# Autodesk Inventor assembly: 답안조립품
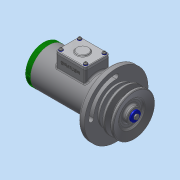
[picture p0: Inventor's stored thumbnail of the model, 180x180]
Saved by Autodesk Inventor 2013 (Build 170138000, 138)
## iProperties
Created: 2017-05
Part Number: 답안조립품
Document SubType Name: Assembly
Designer: dgall
Author: dgall
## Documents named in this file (20)
- C:\Users\dgall\Desktop\470507V1018\답안조립품.iam
- C:\Users\dgall\Desktop\470507V1018\본체.ipt
- C:\Users\dgall\Desktop\470507V1018\V-벨트풀리.ipt
- C:\Users\dgall\Desktop\470507V1018\너트 M10.ipt
- C:\Users\dgall\Desktop\470507V1018\멈춤링 15 x 1.ipt
- C:\Users\dgall\Desktop\470507V1018\멈춤링 35x1.6.ipt
- C:\Users\dgall\Desktop\470507V1018\베어링 15 x 35 x 11.ipt
- C:\Users\dgall\Desktop\470507V1018\볼트 M4 x 10.ipt
- C:\Users\dgall\Desktop\470507V1018\부시1.ipt
- C:\Users\dgall\Desktop\470507V1018\부시2.ipt
- C:\Users\dgall\Desktop\470507V1018\사이드 커버.ipt
- 사이드 커버.ipt
- C:\Users\dgall\Desktop\470507V1018\십자볼트 M3 x 10.ipt
- C:\Users\dgall\Desktop\470507V1018\오일 실 15 25 7.ipt
- C:\Users\dgall\Desktop\470507V1018\와셔 3x6.ipt
- C:\Users\dgall\Desktop\470507V1018\와셔 4x16.ipt
- C:\Users\dgall\Desktop\470507V1018\와셔 10x21.ipt
- C:\Users\dgall\Desktop\470507V1018\축.ipt
- C:\Users\dgall\Desktop\470507V1018\키 4 x 4 x 18.ipt
- C:\Users\dgall\Desktop\470507V1018\탑 커버.ipt
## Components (2 placed, 2 different names)
1. ISO 4017 M4 x 10:1
2. V-벨트풀리:1
